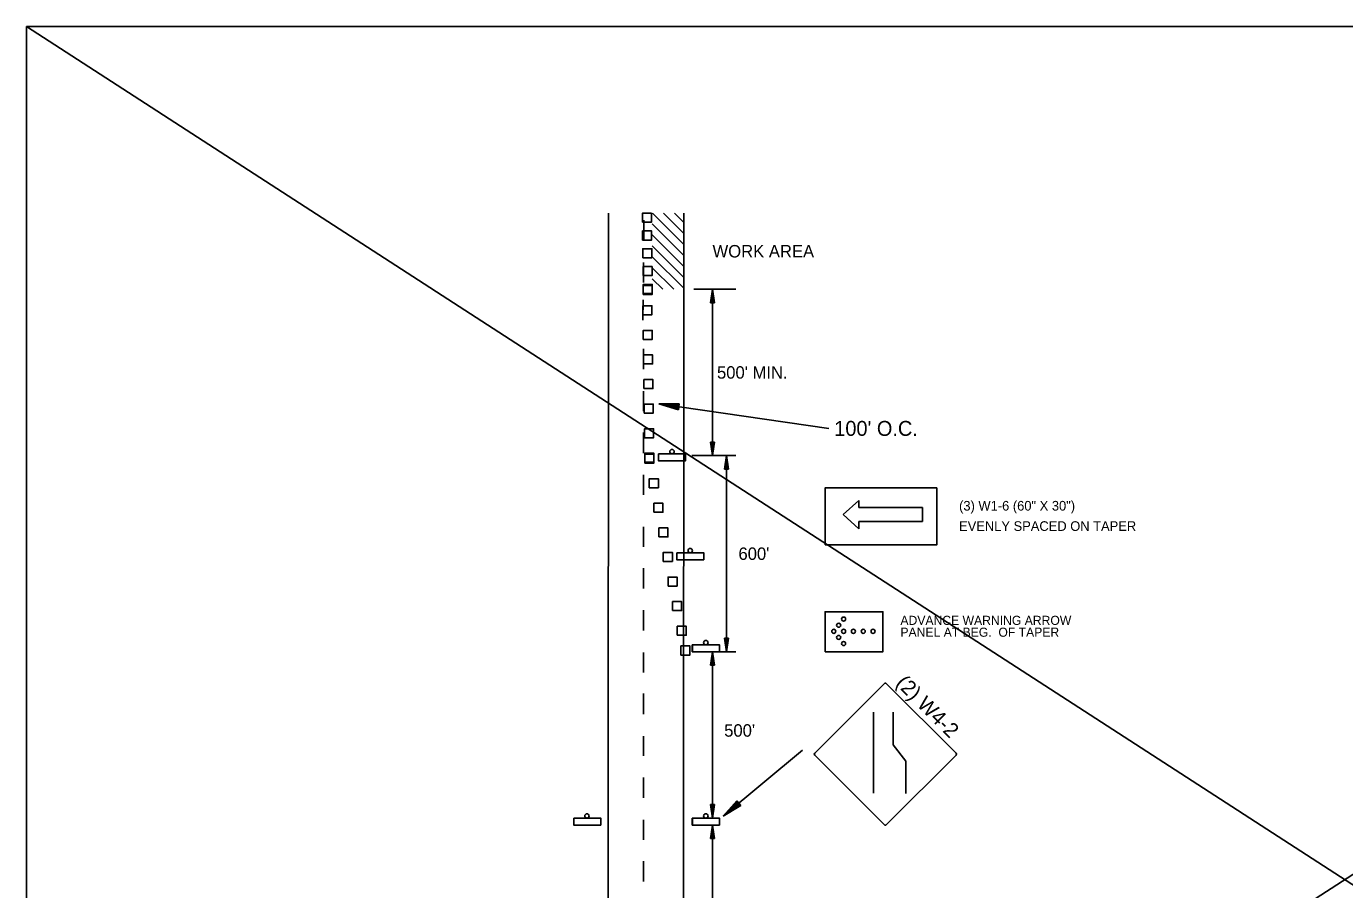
# Model space of a CAD drawing. Extents: x 1374027 to 1374537, y 380415 to 381405.
# Drawn here: x 1374367.1 to 1374452.1, y 381129.5 to 381185.2 of the extents above; entities that cross this region are included whole.
import ezdxf

# ---------------------------------------------------------------- set-up
doc = ezdxf.new("R2010")
doc.units = 0
for name, color, linetype in [('Default', 7, 'Continuous'), ('DSN_DRFT_Junk-No-Plot', 7, 'Continuous'), ('R_Exist Surface', 7, 'Continuous'), ('R_MOT', 7, 'Continuous')]:
    doc.layers.add(name, color=color, linetype=linetype)

msp = doc.modelspace()

# ---------------------------------------------------------------- linework, layer by layer
at = {"layer": 'Default'}
for p, q in [((1374409.473, 381170.41), (1374407.442, 381172.444)), ((1374409.474, 381171.117), (1374407.461, 381173.133)), ((1374409.474, 381171.824), (1374408.168, 381173.132)), ((1374409.474, 381172.532), (1374408.875, 381173.132)), ((1374409.473, 381169.703), (1374407.442, 381171.736)), ((1374409.472, 381168.996), (1374407.442, 381171.029)), ((1374409.472, 381168.289), (1374407.442, 381170.321)), ((1374408.825, 381168.229), (1374407.442, 381169.614)), ((1374408.119, 381168.229), (1374407.442, 381168.906))]:
    msp.add_line(p, q, dxfattribs=at)
msp.add_lwpolyline([(1374418.587, 381144.86), (1374422.311, 381144.86), (1374422.311, 381147.437), (1374418.587, 381147.437)], close=True, dxfattribs=at)
for centre in [(1374419.777, 381146.967), (1374419.145, 381146.178), (1374419.461, 381146.572), (1374419.777, 381146.178), (1374420.41, 381146.178), (1374421.042, 381146.178), (1374421.675, 381146.178), (1374419.461, 381145.783), (1374419.777, 381145.389)]:
    msp.add_circle(centre, 0.131, dxfattribs=at)
at = {"layer": 'DSN_DRFT_Junk-No-Plot'}
for p, q in [((1374367.083, 381075.174), (1374537.083, 381185.174)), ((1374367.083, 381185.174), (1374537.083, 381075.174))]:
    msp.add_line(p, q, dxfattribs=at)
for points in [[(1374367.083, 381185.174), (1374537.083, 381185.174), (1374537.083, 381075.174), (1374367.083, 381075.174)], [(1374367.083, 381185.174), (1374367.083, 381075.174), (1374537.083, 381075.174), (1374537.083, 381185.174)]]:
    msp.add_lwpolyline(points, close=True, dxfattribs=at)
at = {"layer": 'R_Exist Surface'}
for p, q in [((1374404.621, 381173.131), (1374404.581, 381104.045)), ((1374409.48, 381173.131), (1374409.44, 381104.042)), ((1374410.119, 381168.229), (1374412.819, 381168.229)), ((1374411.195, 381167.354), (1374411.326, 381168.229)), ((1374411.217, 381167.354), (1374411.326, 381168.083)), ((1374411.457, 381167.354), (1374411.326, 381168.229)), ((1374411.326, 381157.504), (1374411.326, 381168.229)), ((1374411.435, 381167.354), (1374411.326, 381168.083)), ((1374411.457, 381167.354), (1374411.195, 381167.354)), ((1374411.239, 381167.354), (1374411.326, 381167.932)), ((1374411.261, 381167.354), (1374411.326, 381167.787)), ((1374411.283, 381167.354), (1374411.326, 381167.638)), ((1374411.306, 381167.354), (1374411.326, 381167.492)), ((1374411.413, 381167.354), (1374411.326, 381167.932)), ((1374411.391, 381167.354), (1374411.326, 381167.787)), ((1374411.369, 381167.354), (1374411.326, 381167.638)), ((1374411.347, 381167.354), (1374411.326, 381167.492)), ((1374409.184, 381160.852), (1374407.858, 381160.845)), ((1374418.824, 381159.259), (1374407.858, 381160.845)), ((1374409.127, 381160.463), (1374407.858, 381160.845)), ((1374409.179, 381160.82), (1374408.074, 381160.814)), ((1374409.132, 381160.495), (1374408.074, 381160.814)), ((1374409.174, 381160.787), (1374408.298, 381160.782)), ((1374409.137, 381160.528), (1374408.298, 381160.782)), ((1374409.17, 381160.754), (1374408.514, 381160.75)), ((1374409.142, 381160.561), (1374408.514, 381160.75)), ((1374409.165, 381160.721), (1374408.734, 381160.718)), ((1374409.147, 381160.595), (1374408.734, 381160.718)), ((1374409.16, 381160.688), (1374408.951, 381160.687)), ((1374409.151, 381160.627), (1374408.951, 381160.687)), ((1374409.127, 381160.463), (1374409.184, 381160.852)), ((1374411.195, 381158.378), (1374411.326, 381157.504)), ((1374411.195, 381158.378), (1374411.457, 381158.378)), ((1374411.217, 381158.378), (1374411.326, 381157.65)), ((1374411.239, 381158.378), (1374411.326, 381157.8)), ((1374411.261, 381158.378), (1374411.326, 381157.945)), ((1374411.284, 381158.378), (1374411.326, 381158.094)), ((1374411.306, 381158.378), (1374411.326, 381158.24)), ((1374411.457, 381158.378), (1374411.326, 381157.504)), ((1374411.369, 381158.378), (1374411.326, 381158.094)), ((1374411.413, 381158.378), (1374411.326, 381157.8)), ((1374411.435, 381158.378), (1374411.326, 381157.65)), ((1374411.391, 381158.378), (1374411.326, 381157.945)), ((1374411.347, 381158.378), (1374411.326, 381158.24)), ((1374409.984, 381157.504), (1374412.819, 381157.504)), ((1374412.097, 381156.629), (1374412.228, 381157.504)), ((1374412.118, 381156.629), (1374412.228, 381157.358)), ((1374412.141, 381156.629), (1374412.228, 381157.207)), ((1374412.163, 381156.629), (1374412.228, 381157.062)), ((1374412.359, 381156.629), (1374412.228, 381157.504)), ((1374412.228, 381144.86), (1374412.228, 381157.504)), ((1374412.337, 381156.629), (1374412.228, 381157.358)), ((1374412.315, 381156.629), (1374412.228, 381157.207)), ((1374412.293, 381156.629), (1374412.228, 381157.062)), ((1374412.359, 381156.629), (1374412.097, 381156.629)), ((1374412.185, 381156.629), (1374412.228, 381156.913)), ((1374412.207, 381156.629), (1374412.228, 381156.767)), ((1374412.27, 381156.629), (1374412.228, 381156.913)), ((1374412.248, 381156.629), (1374412.228, 381156.767)), ((1374412.097, 381145.735), (1374412.228, 381144.86)), ((1374412.097, 381145.735), (1374412.359, 381145.735)), ((1374412.118, 381145.735), (1374412.228, 381145.006)), ((1374412.141, 381145.735), (1374412.228, 381145.157)), ((1374412.163, 381145.735), (1374412.228, 381145.302)), ((1374412.185, 381145.735), (1374412.228, 381145.451)), ((1374412.207, 381145.735), (1374412.228, 381145.597)), ((1374412.359, 381145.735), (1374412.228, 381144.86)), ((1374412.271, 381145.735), (1374412.228, 381145.451)), ((1374412.315, 381145.735), (1374412.228, 381145.157)), ((1374412.337, 381145.735), (1374412.228, 381145.006)), ((1374412.293, 381145.735), (1374412.228, 381145.302)), ((1374412.248, 381145.735), (1374412.228, 381145.597)), ((1374410.254, 381144.86), (1374412.819, 381144.86)), ((1374411.195, 381143.986), (1374411.326, 381144.86)), ((1374411.217, 381143.986), (1374411.326, 381144.714)), ((1374411.239, 381143.986), (1374411.326, 381144.564)), ((1374411.261, 381143.986), (1374411.326, 381144.418)), ((1374411.283, 381143.986), (1374411.326, 381144.27)), ((1374411.457, 381143.986), (1374411.326, 381144.86)), ((1374411.326, 381134.135), (1374411.326, 381144.86)), ((1374411.435, 381143.986), (1374411.326, 381144.714)), ((1374411.413, 381143.986), (1374411.326, 381144.564)), ((1374411.391, 381143.986), (1374411.326, 381144.418)), ((1374411.369, 381143.986), (1374411.326, 381144.27)), ((1374411.457, 381143.986), (1374411.195, 381143.986)), ((1374411.306, 381143.986), (1374411.326, 381144.124)), ((1374411.347, 381143.986), (1374411.326, 381144.124)), ((1374417.912, 381138.319), (1374422.411, 381142.819)), ((1374422.526, 381142.819), (1374427.025, 381138.319)), ((1374421.703, 381140.964), (1374421.703, 381135.743)), ((1374422.982, 381140.964), (1374422.982, 381138.87)), ((1374417.137, 381138.516), (1374412.008, 381134.264)), ((1374423.783, 381137.809), (1374422.982, 381138.87)), ((1374422.411, 381133.705), (1374417.912, 381138.204)), ((1374427.025, 381138.204), (1374422.526, 381133.705)), ((1374423.783, 381137.809), (1374423.783, 381135.716)), ((1374423.783, 381137.742), (1374423.783, 381137.809)), ((1374411.195, 381135.01), (1374411.326, 381134.135)), ((1374411.195, 381135.01), (1374411.457, 381135.01)), ((1374411.217, 381135.01), (1374411.326, 381134.281)), ((1374411.239, 381135.01), (1374411.326, 381134.432)), ((1374411.261, 381135.01), (1374411.326, 381134.577)), ((1374411.284, 381135.01), (1374411.326, 381134.726)), ((1374411.306, 381135.01), (1374411.326, 381134.872)), ((1374411.457, 381135.01), (1374411.326, 381134.135)), ((1374411.369, 381135.01), (1374411.326, 381134.726)), ((1374411.413, 381135.01), (1374411.326, 381134.432)), ((1374411.435, 381135.01), (1374411.326, 381134.281)), ((1374411.391, 381135.01), (1374411.326, 381134.577)), ((1374411.347, 381135.01), (1374411.326, 381134.872)), ((1374412.892, 381135.253), (1374412.008, 381134.264)), ((1374413.143, 381134.95), (1374412.008, 381134.264)), ((1374412.913, 381135.227), (1374412.177, 381134.404)), ((1374413.122, 381134.975), (1374412.177, 381134.404)), ((1374412.935, 381135.202), (1374412.351, 381134.548)), ((1374413.101, 381135.001), (1374412.351, 381134.548)), ((1374412.956, 381135.176), (1374412.519, 381134.687)), ((1374413.08, 381135.026), (1374412.519, 381134.687)), ((1374412.977, 381135.151), (1374412.69, 381134.829)), ((1374413.058, 381135.052), (1374412.69, 381134.829)), ((1374412.998, 381135.125), (1374412.858, 381134.969)), ((1374413.038, 381135.077), (1374412.858, 381134.969)), ((1374413.143, 381134.95), (1374412.892, 381135.253)), ((1374411.195, 381132.813), (1374411.326, 381133.687)), ((1374411.217, 381132.813), (1374411.326, 381133.541)), ((1374411.239, 381132.813), (1374411.326, 381133.391)), ((1374411.261, 381132.813), (1374411.326, 381133.245)), ((1374411.457, 381132.813), (1374411.326, 381133.687)), ((1374411.326, 381121.157), (1374411.326, 381133.687)), ((1374411.435, 381132.813), (1374411.326, 381133.541)), ((1374411.413, 381132.813), (1374411.326, 381133.391)), ((1374411.391, 381132.813), (1374411.326, 381133.245)), ((1374411.457, 381132.813), (1374411.195, 381132.813)), ((1374411.283, 381132.813), (1374411.326, 381133.097)), ((1374411.306, 381132.813), (1374411.326, 381132.951)), ((1374411.369, 381132.813), (1374411.326, 381133.097)), ((1374411.347, 381132.813), (1374411.326, 381132.951))]:
    msp.add_line(p, q, dxfattribs=at)
for points in [[(1374406.804, 381172.549), (1374407.387, 381172.549), (1374407.387, 381173.131), (1374406.804, 381173.131)], [(1374406.817, 381171.401), (1374407.4, 381171.401), (1374407.4, 381171.984), (1374406.817, 381171.984)], [(1374406.831, 381170.254), (1374407.414, 381170.254), (1374407.414, 381170.837), (1374406.831, 381170.837)], [(1374406.844, 381169.107), (1374407.427, 381169.107), (1374407.427, 381169.69), (1374406.844, 381169.69)], [(1374406.858, 381167.96), (1374407.441, 381167.96), (1374407.441, 381168.543), (1374406.858, 381168.543)], [(1374406.858, 381167.96), (1374407.441, 381167.96), (1374407.441, 381168.543), (1374406.858, 381168.543)], [(1374406.859, 381167.892), (1374407.442, 381167.892), (1374407.442, 381168.475), (1374406.859, 381168.475)], [(1374406.859, 381167.892), (1374407.442, 381167.892), (1374407.442, 381168.475), (1374406.859, 381168.475)], [(1374406.839, 381166.581), (1374407.422, 381166.581), (1374407.422, 381167.164), (1374406.839, 381167.164)], [(1374406.859, 381164.996), (1374407.442, 381164.996), (1374407.442, 381165.579), (1374406.859, 381165.579)], [(1374406.88, 381163.412), (1374407.462, 381163.412), (1374407.462, 381163.994), (1374406.88, 381163.994)], [(1374406.9, 381161.827), (1374407.483, 381161.827), (1374407.483, 381162.41), (1374406.9, 381162.41)], [(1374406.92, 381160.242), (1374407.503, 381160.242), (1374407.503, 381160.825), (1374406.92, 381160.825)], [(1374406.941, 381158.657), (1374407.523, 381158.657), (1374407.523, 381159.24), (1374406.941, 381159.24)], [(1374406.961, 381157.072), (1374407.544, 381157.072), (1374407.544, 381157.655), (1374406.961, 381157.655)], [(1374406.961, 381157.02), (1374407.544, 381157.02), (1374407.544, 381157.603), (1374406.961, 381157.603)], [(1374407.839, 381157.623), (1374409.588, 381157.623), (1374409.588, 381157.175), (1374407.839, 381157.175)], [(1374407.848, 381157.623), (1374409.588, 381157.623), (1374409.588, 381157.175), (1374407.848, 381157.175)], [(1374407.25, 381155.435), (1374407.833, 381155.435), (1374407.833, 381156.018), (1374407.25, 381156.018)], [(1374407.543, 381153.85), (1374408.126, 381153.85), (1374408.126, 381154.433), (1374407.543, 381154.433)], [(1374407.866, 381152.265), (1374408.449, 381152.265), (1374408.449, 381152.848), (1374407.866, 381152.848)], [(1374408.152, 381150.68), (1374408.735, 381150.68), (1374408.735, 381151.263), (1374408.152, 381151.263)], [(1374409.015, 381151.243), (1374410.763, 381151.243), (1374410.763, 381150.795), (1374409.015, 381150.795)], [(1374409.024, 381151.243), (1374410.763, 381151.243), (1374410.763, 381150.795), (1374409.024, 381150.795)], [(1374408.455, 381149.095), (1374409.037, 381149.095), (1374409.037, 381149.678), (1374408.455, 381149.678)], [(1374408.75, 381147.511), (1374409.333, 381147.511), (1374409.333, 381148.093), (1374408.75, 381148.093)], [(1374409.049, 381145.926), (1374409.632, 381145.926), (1374409.632, 381146.509), (1374409.049, 381146.509)], [(1374409.284, 381144.651), (1374409.866, 381144.651), (1374409.866, 381145.234), (1374409.284, 381145.234)], [(1374409.284, 381144.651), (1374409.866, 381144.651), (1374409.866, 381145.234), (1374409.284, 381145.234)], [(1374410.023, 381145.309), (1374411.771, 381145.309), (1374411.771, 381144.86), (1374410.023, 381144.86)], [(1374410.032, 381145.309), (1374411.771, 381145.309), (1374411.771, 381144.86), (1374410.032, 381144.86)], [(1374402.375, 381134.135), (1374404.114, 381134.135), (1374404.114, 381133.687), (1374402.375, 381133.687)], [(1374402.375, 381134.135), (1374404.114, 381134.135), (1374404.114, 381133.687), (1374402.375, 381133.687)], [(1374410.023, 381134.135), (1374411.771, 381134.135), (1374411.771, 381133.687), (1374410.023, 381133.687)], [(1374410.032, 381134.135), (1374411.771, 381134.135), (1374411.771, 381133.687), (1374410.032, 381133.687)]]:
    msp.add_lwpolyline(points, close=True, dxfattribs=at)
for points in [[(1374406.887, 381172.682), (1374406.886, 381171.366)], [(1374406.885, 381169.949), (1374406.885, 381168.667)], [(1374406.843, 381167.556), (1374406.842, 381166.241)], [(1374406.884, 381164.387), (1374406.883, 381163.071)], [(1374406.882, 381161.654), (1374406.881, 381160.372)], [(1374406.881, 381158.988), (1374406.88, 381157.672)], [(1374406.879, 381156.255), (1374406.878, 381154.972)], [(1374406.88, 381152.914), (1374406.88, 381151.632)], [(1374406.879, 381150.248), (1374406.878, 381148.932)], [(1374406.879, 381150.216), (1374406.878, 381148.934)], [(1374406.877, 381147.55), (1374406.876, 381146.234)], [(1374406.875, 381144.817), (1374406.875, 381143.534)], [(1374406.874, 381142.161), (1374406.873, 381140.845)], [(1374406.872, 381139.427), (1374406.872, 381138.145)], [(1374406.871, 381136.761), (1374406.87, 381135.445)], [(1374406.869, 381134.028), (1374406.869, 381132.746)], [(1374406.868, 381131.362), (1374406.867, 381130.046)]]:
    msp.add_lwpolyline(points, dxfattribs=at)
for centre in [(1374408.712, 381157.764), (1374409.887, 381151.384), (1374410.895, 381145.45), (1374403.228, 381134.276), (1374410.895, 381134.276)]:
    msp.add_ellipse(centre, major_axis=(0, 0.141), ratio=0.999914, dxfattribs=at)
for centre, major_axis, start_param, end_param in [((1374422.469, 381142.761), (0, -0.0816), 2.356194, 3.926991), ((1374417.97, 381138.262), (0, -0.0816), 3.926991, 5.497786), ((1374426.967, 381138.262), (0, 0.0816), 3.926992, 5.497787), ((1374422.469, 381133.763), (0, -0.0816), 5.497786, 7.068585)]:
    msp.add_ellipse(centre, major_axis=major_axis, ratio=0.999914, start_param=start_param, end_param=end_param, dxfattribs=at)
at = {"layer": 'R_MOT'}
for p, q in [((1374419.76, 381153.704), (1374420.762, 381154.618)), ((1374420.762, 381154.161), (1374420.762, 381154.618)), ((1374420.762, 381152.79), (1374419.76, 381153.704)), ((1374424.868, 381154.161), (1374420.762, 381154.161)), ((1374424.868, 381153.247), (1374424.868, 381154.161)), ((1374424.868, 381153.247), (1374420.762, 381153.247)), ((1374420.762, 381153.247), (1374420.762, 381152.79))]:
    msp.add_line(p, q, dxfattribs=at)
msp.add_lwpolyline([(1374418.587, 381151.743), (1374425.785, 381151.743), (1374425.785, 381155.424), (1374418.587, 381155.424)], close=True, dxfattribs=at)

# ---------------------------------------------------------------- texts
at = {"layer": 'Default'}
for s, p in [('ADVANCE WARNING ARROW', (1374423.441, 381146.592)), ('PANEL AT BEG.  OF TAPER', (1374423.441, 381145.828))]:
    msp.add_text(s, height=0.5862, dxfattribs=at).set_placement(p)
at = {"layer": 'R_Exist Surface'}
for s, height, p in [('WORK AREA', 0.8015, (1374411.326, 381170.279)), ("500' MIN.", 0.8015, (1374411.613, 381162.465)), ("100' O.C.", 0.9617, (1374419.174, 381158.778)), ("600'", 0.8015, (1374412.998, 381150.781)), ("500'", 0.8015, (1374412.077, 381139.386))]:
    msp.add_text(s, height=height, dxfattribs=at).set_placement(p)
msp.add_text('(2) W4-2', height=0.9617, rotation=314.99383, dxfattribs=at).set_placement((1374423.09, 381142.771))
at = {"layer": 'R_MOT'}
for s, p in [('(3) W1-6 (60" X 30")', (1374427.223, 381153.96)), ('EVENLY SPACED ON TAPER', (1374427.223, 381152.65))]:
    msp.add_text(s, height=0.6222, rotation=0.00754, dxfattribs=at).set_placement(p)

doc.saveas('drawing.dxf')
